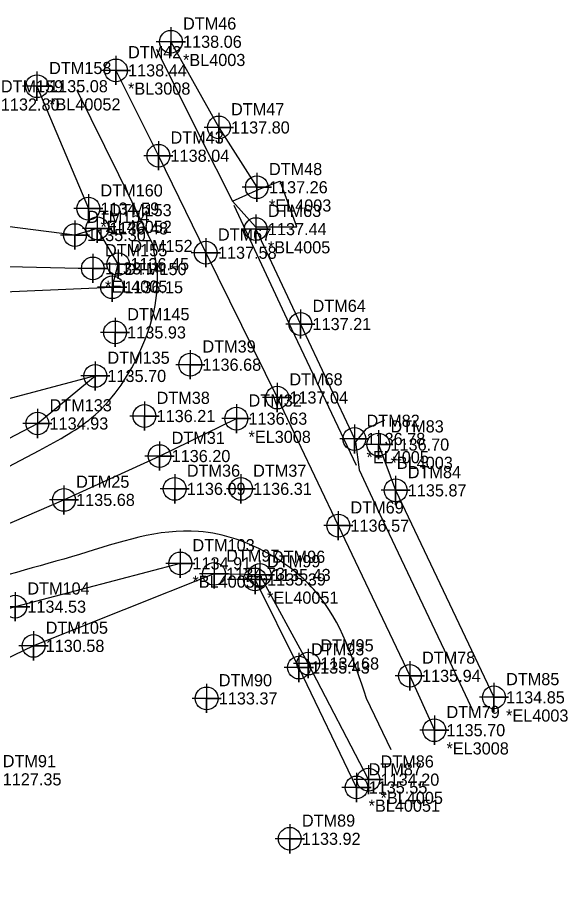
# Model space of a CAD drawing. Extents: x 1286409 to 1286829, y 857931 to 858308.
# Drawn here: x 1286715.3 to 1286828.6, y 858130 to 858308 of the extents above; entities that cross this region are included whole.
import ezdxf

# ---------------------------------------------------------------- set-up
doc = ezdxf.new("R2010")
doc.units = 0
for name, color, linetype in [('Exist DTM Breakline', 7, 'Continuous'), ('Exist DTM Breakline Cogo Comment', 7, 'Continuous'), ('Exist DTM Breakline Cogo Elevation', 7, 'Continuous'), ('Exist DTM Breakline Cogo Number', 7, 'Continuous'), ('Exist DTM Breakline Cogo Point CELL', 7, 'Continuous'), ('Exist DTM Crownline', 7, 'Continuous'), ('Exist DTM Crownline Cogo Comment', 7, 'Continuous'), ('Exist DTM Crownline Cogo Elevation', 7, 'Continuous'), ('Exist DTM Crownline Cogo Number', 7, 'Continuous'), ('Exist DTM Crownline Cogo Point CELL', 7, 'Continuous'), ('Exist DTM Drainline', 7, 'Continuous'), ('Exist DTM Drainline Cogo Comment', 7, 'Continuous'), ('Exist DTM Drainline Cogo Elevation', 7, 'Continuous'), ('Exist DTM Drainline Cogo Number', 7, 'Continuous'), ('Exist DTM Drainline Cogo Point CELL', 7, 'Continuous'), ('Exist DTM Regular Point CELL', 7, 'Continuous'), ('Exist DTM Regular Point Cogo Elevation', 7, 'Continuous'), ('Exist DTM Regular Point Cogo Number', 7, 'Continuous'), ('Exist Roads EOP', 7, 'Continuous'), ('Exist Roads EOP Other', 7, 'Continuous'), ('Exist Roads EOT', 7, 'Continuous')]:
    doc.layers.add(name, color=color, linetype=linetype)

msp = doc.modelspace()

# ---------------------------------------------------------------- linework, layer by layer
at = {"layer": 'Exist DTM Breakline'}
msp.add_line((1286719.354, 858293.793), (1286729.923, 858268.579), dxfattribs=at)
for points in [[(1286632.493, 858242.571), (1286660.074, 858248.148), (1286685.945, 858249.23), (1286699.802, 858250.923), (1286734.824, 858252.386), (1286736.062, 858257.139), (1286731.751, 858264.514), (1286727.165, 858263.134), (1286687.944, 858268.125), (1286659.976, 858268.899), (1286650.61, 858279.628)], [(1286764.385, 858264.363), (1286773.573, 858244.809), (1286784.678, 858221.142)], [(1286616.952, 858240.566), (1286629.155, 858244.707), (1286658.287, 858253.478), (1286686.461, 858252.975), (1286698.943, 858257.032), (1286730.846, 858256.269)], [(1286748.85, 858195.515), (1286714.87, 858186.6), (1286669.883, 858173.996), (1286664.879, 858174.577), (1286666.033, 858171.901), (1286676.529, 858166.124), (1286675.191, 858165.032), (1286664.853, 858171.436), (1286655.406, 858192.72), (1286657.428, 858206.193), (1286658.087, 858204.832), (1286657.611, 858191.117), (1286680.683, 858204.103), (1286719.44, 858224.327), (1286731.354, 858234.119), (1286690.517, 858223.266), (1286655.768, 858212.7), (1286632.397, 858220.726)], [(1286787.57, 858150.977), (1286775.181, 858174.894), (1286765.217, 858193.137), (1286755.797, 858193.361), (1286718.64, 858178.527), (1286680.221, 858159.977), (1286675.641, 858160.401), (1286671.867, 858162.031), (1286662.339, 858153.405), (1286673.303, 858134.067), (1286682.298, 858123.811), (1286697.007, 858100.077), (1286709.742, 858055.54)], [(1286785.117, 858149.369), (1286773.255, 858174.07), (1286764.227, 858192.206)]]:
    msp.add_lwpolyline(points, dxfattribs=at)
at = {"layer": 'Exist DTM Breakline Cogo Point CELL'}
for points in [[(1286719.354, 858296.793), (1286719.354, 858290.793), (1286719.354, 858293.793), (1286722.354, 858293.793), (1286716.354, 858293.793)], [(1286729.923, 858271.579), (1286729.923, 858265.579), (1286729.923, 858268.579), (1286732.923, 858268.579), (1286726.923, 858268.579)], [(1286731.751, 858267.514), (1286731.751, 858261.514), (1286731.751, 858264.514), (1286734.751, 858264.514), (1286728.751, 858264.514)], [(1286764.385, 858267.363), (1286764.385, 858261.363), (1286764.385, 858264.363), (1286767.385, 858264.363), (1286761.385, 858264.363)], [(1286727.165, 858266.134), (1286727.165, 858260.134), (1286727.165, 858263.134), (1286730.165, 858263.134), (1286724.165, 858263.134)], [(1286736.062, 858260.139), (1286736.062, 858254.139), (1286736.062, 858257.139), (1286739.062, 858257.139), (1286733.062, 858257.139)], [(1286730.846, 858259.269), (1286730.846, 858253.269), (1286730.846, 858256.269), (1286733.846, 858256.269), (1286727.846, 858256.269)], [(1286734.824, 858255.386), (1286734.824, 858249.386), (1286734.824, 858252.386), (1286737.824, 858252.386), (1286731.824, 858252.386)], [(1286773.573, 858247.809), (1286773.573, 858241.809), (1286773.573, 858244.809), (1286776.573, 858244.809), (1286770.573, 858244.809)], [(1286731.354, 858237.119), (1286731.354, 858231.119), (1286731.354, 858234.119), (1286734.354, 858234.119), (1286728.354, 858234.119)], [(1286719.44, 858227.327), (1286719.44, 858221.327), (1286719.44, 858224.327), (1286722.44, 858224.327), (1286716.44, 858224.327)], [(1286784.678, 858224.142), (1286784.678, 858218.142), (1286784.678, 858221.142), (1286787.678, 858221.142), (1286781.678, 858221.142)], [(1286748.85, 858198.515), (1286748.85, 858192.515), (1286748.85, 858195.515), (1286751.85, 858195.515), (1286745.85, 858195.515)], [(1286755.797, 858196.361), (1286755.797, 858190.361), (1286755.797, 858193.361), (1286758.797, 858193.361), (1286752.797, 858193.361)], [(1286765.217, 858196.137), (1286765.217, 858190.137), (1286765.217, 858193.137), (1286768.217, 858193.137), (1286762.217, 858193.137)], [(1286764.227, 858195.206), (1286764.227, 858189.206), (1286764.227, 858192.206), (1286767.227, 858192.206), (1286761.227, 858192.206)], [(1286714.87, 858189.6), (1286714.87, 858183.6), (1286714.87, 858186.6), (1286717.87, 858186.6), (1286711.87, 858186.6)], [(1286718.64, 858181.527), (1286718.64, 858175.527), (1286718.64, 858178.527), (1286721.64, 858178.527), (1286715.64, 858178.527)], [(1286775.181, 858177.894), (1286775.181, 858171.894), (1286775.181, 858174.894), (1286778.181, 858174.894), (1286772.181, 858174.894)], [(1286773.255, 858177.07), (1286773.255, 858171.07), (1286773.255, 858174.07), (1286776.255, 858174.07), (1286770.255, 858174.07)], [(1286787.57, 858153.977), (1286787.57, 858147.977), (1286787.57, 858150.977), (1286790.57, 858150.977), (1286784.57, 858150.977)], [(1286785.117, 858152.369), (1286785.117, 858146.369), (1286785.117, 858149.369), (1286788.117, 858149.369), (1286782.117, 858149.369)]]:
    msp.add_lwpolyline(points, dxfattribs=at)
for centre in [(1286719.354, 858293.793), (1286729.923, 858268.579), (1286727.165, 858263.134), (1286731.751, 858264.514), (1286764.385, 858264.363), (1286730.846, 858256.269), (1286736.062, 858257.139), (1286734.824, 858252.386), (1286773.573, 858244.809), (1286731.354, 858234.119), (1286719.44, 858224.327), (1286784.678, 858221.142), (1286748.85, 858195.515), (1286755.797, 858193.361), (1286764.227, 858192.206), (1286765.217, 858193.137), (1286714.87, 858186.6), (1286718.64, 858178.527), (1286773.255, 858174.07), (1286775.181, 858174.894), (1286787.57, 858150.977), (1286785.117, 858149.369)]:
    msp.add_circle(centre, 2.344, dxfattribs=at)
at = {"layer": 'Exist DTM Crownline'}
for points in [[(1286735.599, 858297.048), (1286744.342, 858279.468), (1286754.096, 858259.499), (1286768.799, 858229.676), (1286781.376, 858203.29), (1286796.098, 858172.359), (1286801.137, 858161.163)], [(1286661.096, 858181.88), (1286698.94, 858197.382), (1286724.907, 858208.588), (1286744.568, 858217.621), (1286760.393, 858225.322)]]:
    msp.add_lwpolyline(points, dxfattribs=at)
at = {"layer": 'Exist DTM Crownline Cogo Point CELL'}
for points in [[(1286735.599, 858300.048), (1286735.599, 858294.048), (1286735.599, 858297.048), (1286738.599, 858297.048), (1286732.599, 858297.048)], [(1286744.342, 858282.468), (1286744.342, 858276.468), (1286744.342, 858279.468), (1286747.342, 858279.468), (1286741.342, 858279.468)], [(1286754.096, 858262.499), (1286754.096, 858256.499), (1286754.096, 858259.499), (1286757.096, 858259.499), (1286751.096, 858259.499)], [(1286768.799, 858232.676), (1286768.799, 858226.676), (1286768.799, 858229.676), (1286771.799, 858229.676), (1286765.799, 858229.676)], [(1286760.393, 858228.322), (1286760.393, 858222.322), (1286760.393, 858225.322), (1286763.393, 858225.322), (1286757.393, 858225.322)], [(1286744.568, 858220.621), (1286744.568, 858214.621), (1286744.568, 858217.621), (1286747.568, 858217.621), (1286741.568, 858217.621)], [(1286724.907, 858211.588), (1286724.907, 858205.588), (1286724.907, 858208.588), (1286727.907, 858208.588), (1286721.907, 858208.588)], [(1286781.376, 858206.29), (1286781.376, 858200.29), (1286781.376, 858203.29), (1286784.376, 858203.29), (1286778.376, 858203.29)], [(1286796.098, 858175.359), (1286796.098, 858169.359), (1286796.098, 858172.359), (1286799.098, 858172.359), (1286793.098, 858172.359)], [(1286801.137, 858164.163), (1286801.137, 858158.163), (1286801.137, 858161.163), (1286804.137, 858161.163), (1286798.137, 858161.163)]]:
    msp.add_lwpolyline(points, dxfattribs=at)
for centre in [(1286735.599, 858297.048), (1286744.342, 858279.468), (1286754.096, 858259.499), (1286768.799, 858229.676), (1286760.393, 858225.322), (1286744.568, 858217.621), (1286724.907, 858208.588), (1286781.376, 858203.29), (1286796.098, 858172.359), (1286801.137, 858161.163)]:
    msp.add_circle(centre, 2.344, dxfattribs=at)
at = {"layer": 'Exist DTM Drainline'}
for points in [[(1286746.911, 858302.946), (1286756.793, 858285.299), (1286764.601, 858272.981)], [(1286789.614, 858219.985), (1286793.174, 858210.562), (1286813.405, 858167.931)]]:
    msp.add_lwpolyline(points, dxfattribs=at)
at = {"layer": 'Exist DTM Drainline Cogo Point CELL'}
for points in [[(1286746.911, 858305.946), (1286746.911, 858299.946), (1286746.911, 858302.946), (1286749.911, 858302.946), (1286743.911, 858302.946)], [(1286756.793, 858288.299), (1286756.793, 858282.299), (1286756.793, 858285.299), (1286759.793, 858285.299), (1286753.793, 858285.299)], [(1286764.601, 858275.981), (1286764.601, 858269.981), (1286764.601, 858272.981), (1286767.601, 858272.981), (1286761.601, 858272.981)], [(1286789.614, 858222.985), (1286789.614, 858216.985), (1286789.614, 858219.985), (1286792.614, 858219.985), (1286786.614, 858219.985)], [(1286793.174, 858213.562), (1286793.174, 858207.562), (1286793.174, 858210.562), (1286796.174, 858210.562), (1286790.174, 858210.562)], [(1286813.405, 858170.931), (1286813.405, 858164.931), (1286813.405, 858167.931), (1286816.405, 858167.931), (1286810.405, 858167.931)]]:
    msp.add_lwpolyline(points, dxfattribs=at)
for centre in [(1286746.911, 858302.946), (1286756.793, 858285.299), (1286764.601, 858272.981), (1286789.614, 858219.985), (1286793.174, 858210.562), (1286813.405, 858167.931)]:
    msp.add_circle(centre, 2.344, dxfattribs=at)
at = {"layer": 'Exist DTM Regular Point CELL'}
for points in [[(1286735.427, 858246.086), (1286735.427, 858240.086), (1286735.427, 858243.086), (1286738.427, 858243.086), (1286732.427, 858243.086)], [(1286750.908, 858239.44), (1286750.908, 858233.44), (1286750.908, 858236.44), (1286753.908, 858236.44), (1286747.908, 858236.44)], [(1286741.474, 858228.862), (1286741.474, 858222.862), (1286741.474, 858225.862), (1286744.474, 858225.862), (1286738.474, 858225.862)], [(1286747.696, 858213.864), (1286747.696, 858207.864), (1286747.696, 858210.864), (1286750.696, 858210.864), (1286744.696, 858210.864)], [(1286761.334, 858213.859), (1286761.334, 858207.859), (1286761.334, 858210.859), (1286764.334, 858210.859), (1286758.334, 858210.859)], [(1286754.272, 858170.708), (1286754.272, 858164.708), (1286754.272, 858167.708), (1286757.272, 858167.708), (1286751.272, 858167.708)], [(1286771.379, 858141.796), (1286771.379, 858135.796), (1286771.379, 858138.796), (1286774.379, 858138.796), (1286768.379, 858138.796)]]:
    msp.add_lwpolyline(points, dxfattribs=at)
for centre in [(1286735.427, 858243.086), (1286750.908, 858236.44), (1286741.474, 858225.862), (1286747.696, 858210.864), (1286761.334, 858210.859), (1286754.272, 858167.708), (1286771.379, 858138.796)]:
    msp.add_circle(centre, 2.344, dxfattribs=at)
at = {"layer": 'Exist Roads EOP'}
for points in [[(1286743.978, 858301.417), (1286752.786, 858283.563), (1286759.601, 858270.089), (1286764.333, 858264.847), (1286772.856, 858264.84), (1286769.432, 858274.234)], [(1286743.12, 858261.304), (1286736.171, 858275.528), (1286727.62, 858292.921)], [(1286790.857, 858225.016), (1286787.036, 858223.157), (1286784.933, 858220.568), (1286785.668, 858214.767), (1286789.334, 858206.964), (1286803.786, 858176.42), (1286809.051, 858165.132)], [(1286658.291, 858188.167), (1286695.619, 858206.081), (1286719.784, 858218.735)], [(1286792.255, 858157.123), (1286787.169, 858167.69)]]:
    msp.add_lwpolyline(points, dxfattribs=at)
for points in [[(1286719.784, 858218.735), (1286731.305, 858226.117), (1286740.715, 858239.543), (1286744.061, 858255.861), (1286743.12, 858261.304)], [(1286787.169, 858167.69), (1286776.787, 858189.619), (1286767.655, 858197.136), (1286752.603, 858202.097), (1286728.107, 858197.379), (1286702.359, 858189.909), (1286664.079, 858174.593)]]:
    msp.add_spline(points, degree=3, dxfattribs=at)
at = {"layer": 'Exist Roads EOP Other'}
msp.add_lwpolyline([(1286759.601, 858270.099), (1286765.099, 858272.585), (1286769.37, 858274.255)], dxfattribs=at)
at = {"layer": 'Exist Roads EOT'}
msp.add_lwpolyline([(1286759.843, 858269.297), (1286771.707, 858243.844), (1286785.073, 858215.744)], dxfattribs=at)

# ---------------------------------------------------------------- texts
at = {"layer": 'Exist DTM Breakline Cogo Comment'}
for s, p in [('*BL40052', (1286721.854, 858288.793)), ('*EL40052', (1286732.423, 858263.579)), ('*BL4005', (1286766.885, 858259.363)), ('*EL4005', (1286733.346, 858251.269)), ('*EL4005', (1286787.178, 858216.142)), ('*BL40051', (1286751.35, 858190.515)), ('*EL40051', (1286766.727, 858187.206)), ('*BL4005', (1286790.07, 858145.977)), ('*BL40051', (1286787.617, 858144.369))]:
    msp.add_text(s, height=2.5, dxfattribs=at).set_placement(p)
at = {"layer": 'Exist DTM Breakline Cogo Elevation'}
for s, p in [('1135.08', (1286721.854, 858292.543)), ('1134.59', (1286732.423, 858267.329)), ('1136.48', (1286734.251, 858263.264)), ('1137.44', (1286766.885, 858263.113)), ('1135.30', (1286729.665, 858261.884)), ('1136.45', (1286738.562, 858255.889)), ('1133.14', (1286733.346, 858255.019)), ('1136.15', (1286737.324, 858251.136)), ('1137.21', (1286776.073, 858243.559)), ('1135.70', (1286733.854, 858232.869)), ('1134.93', (1286721.94, 858223.077)), ('1136.78', (1286787.178, 858219.892)), ('1134.91', (1286751.35, 858194.265)), ('1134.73', (1286758.297, 858192.111)), ('1135.43', (1286767.717, 858191.887)), ('1135.39', (1286766.727, 858190.956)), ('1134.53', (1286717.37, 858185.35)), ('1130.58', (1286721.14, 858177.277)), ('1134.68', (1286777.681, 858173.644)), ('1135.43', (1286775.755, 858172.82)), ('1134.20', (1286790.07, 858149.727)), ('1135.55', (1286787.617, 858148.119))]:
    msp.add_text(s, height=2.5, dxfattribs=at).set_placement(p)
at = {"layer": 'Exist DTM Breakline Cogo Number'}
for s, p in [('DTM158', (1286721.854, 858296.293)), ('DTM160', (1286732.423, 858271.079)), ('DTM153', (1286734.251, 858267.014)), ('DTM63', (1286766.885, 858266.863)), ('DTM154', (1286729.665, 858265.634)), ('DTM152', (1286738.562, 858259.639)), ('DTM155', (1286733.346, 858258.769)), ('DTM150', (1286737.324, 858254.886)), ('DTM64', (1286776.073, 858247.309)), ('DTM135', (1286733.854, 858236.619)), ('DTM133', (1286721.94, 858226.827)), ('DTM82', (1286787.178, 858223.642)), ('DTM103', (1286751.35, 858198.015)), ('DTM97', (1286758.297, 858195.861)), ('DTM96', (1286767.717, 858195.637)), ('DTM99', (1286766.727, 858194.706)), ('DTM104', (1286717.37, 858189.1)), ('DTM105', (1286721.14, 858181.027)), ('DTM95', (1286777.681, 858177.394)), ('DTM93', (1286775.755, 858176.57)), ('DTM86', (1286790.07, 858153.477)), ('DTM87', (1286787.617, 858151.869))]:
    msp.add_text(s, height=2.5, dxfattribs=at).set_placement(p)
at = {"layer": 'Exist DTM Crownline Cogo Comment'}
for s, p in [('*BL3008', (1286738.099, 858292.048)), ('*EL3008', (1286762.893, 858220.322)), ('*EL3008', (1286803.637, 858156.163))]:
    msp.add_text(s, height=2.5, dxfattribs=at).set_placement(p)
at = {"layer": 'Exist DTM Crownline Cogo Elevation'}
for s, p in [('1138.44', (1286738.099, 858295.798)), ('1138.04', (1286746.842, 858278.218)), ('1137.58', (1286756.596, 858258.249)), ('1137.04', (1286771.299, 858228.426)), ('1136.63', (1286762.893, 858224.072)), ('1136.20', (1286747.068, 858216.371)), ('1135.68', (1286727.407, 858207.338)), ('1136.57', (1286783.876, 858202.04)), ('1135.94', (1286798.598, 858171.109)), ('1135.70', (1286803.637, 858159.913))]:
    msp.add_text(s, height=2.5, dxfattribs=at).set_placement(p)
at = {"layer": 'Exist DTM Crownline Cogo Number'}
for s, p in [('DTM42', (1286738.099, 858299.548)), ('DTM43', (1286746.842, 858281.968)), ('DTM67', (1286756.596, 858261.999)), ('DTM68', (1286771.299, 858232.176)), ('DTM32', (1286762.893, 858227.822)), ('DTM31', (1286747.068, 858220.121)), ('DTM25', (1286727.407, 858211.088)), ('DTM69', (1286783.876, 858205.79)), ('DTM78', (1286798.598, 858174.859)), ('DTM79', (1286803.637, 858163.663))]:
    msp.add_text(s, height=2.5, dxfattribs=at).set_placement(p)
at = {"layer": 'Exist DTM Drainline Cogo Comment'}
for s, p in [('*BL4003', (1286749.411, 858297.946)), ('*EL4003', (1286767.101, 858267.981)), ('*BL4003', (1286792.114, 858214.985)), ('*EL4003', (1286815.905, 858162.931))]:
    msp.add_text(s, height=2.5, dxfattribs=at).set_placement(p)
at = {"layer": 'Exist DTM Drainline Cogo Elevation'}
for s, p in [('1138.06', (1286749.411, 858301.696)), ('1137.80', (1286759.293, 858284.049)), ('1137.26', (1286767.101, 858271.731)), ('1136.70', (1286792.114, 858218.735)), ('1135.87', (1286795.674, 858209.312)), ('1134.85', (1286815.905, 858166.681))]:
    msp.add_text(s, height=2.5, dxfattribs=at).set_placement(p)
at = {"layer": 'Exist DTM Drainline Cogo Number'}
for s, p in [('DTM46', (1286749.411, 858305.446)), ('DTM47', (1286759.293, 858287.799)), ('DTM48', (1286767.101, 858275.481)), ('DTM83', (1286792.114, 858222.485)), ('DTM84', (1286795.674, 858213.062)), ('DTM85', (1286815.905, 858170.431))]:
    msp.add_text(s, height=2.5, dxfattribs=at).set_placement(p)
at = {"layer": 'Exist DTM Regular Point Cogo Elevation'}
for s, p in [('1132.80', (1286711.922, 858288.775)), ('1135.93', (1286737.927, 858241.836)), ('1136.68', (1286753.408, 858235.19)), ('1136.21', (1286743.974, 858224.612)), ('1136.09', (1286750.196, 858209.614)), ('1136.31', (1286763.834, 858209.609)), ('1133.37', (1286756.772, 858166.458)), ('1127.35', (1286712.306, 858149.796)), ('1133.92', (1286773.879, 858137.546))]:
    msp.add_text(s, height=2.5, dxfattribs=at).set_placement(p)
at = {"layer": 'Exist DTM Regular Point Cogo Number'}
for s, p in [('DTM159', (1286711.922, 858292.525)), ('DTM145', (1286737.927, 858245.586)), ('DTM39', (1286753.408, 858238.94)), ('DTM38', (1286743.974, 858228.362)), ('DTM36', (1286750.196, 858213.364)), ('DTM37', (1286763.834, 858213.359)), ('DTM90', (1286756.772, 858170.208)), ('DTM91', (1286712.306, 858153.546)), ('DTM89', (1286773.879, 858141.296))]:
    msp.add_text(s, height=2.5, dxfattribs=at).set_placement(p)

doc.saveas('drawing.dxf')
